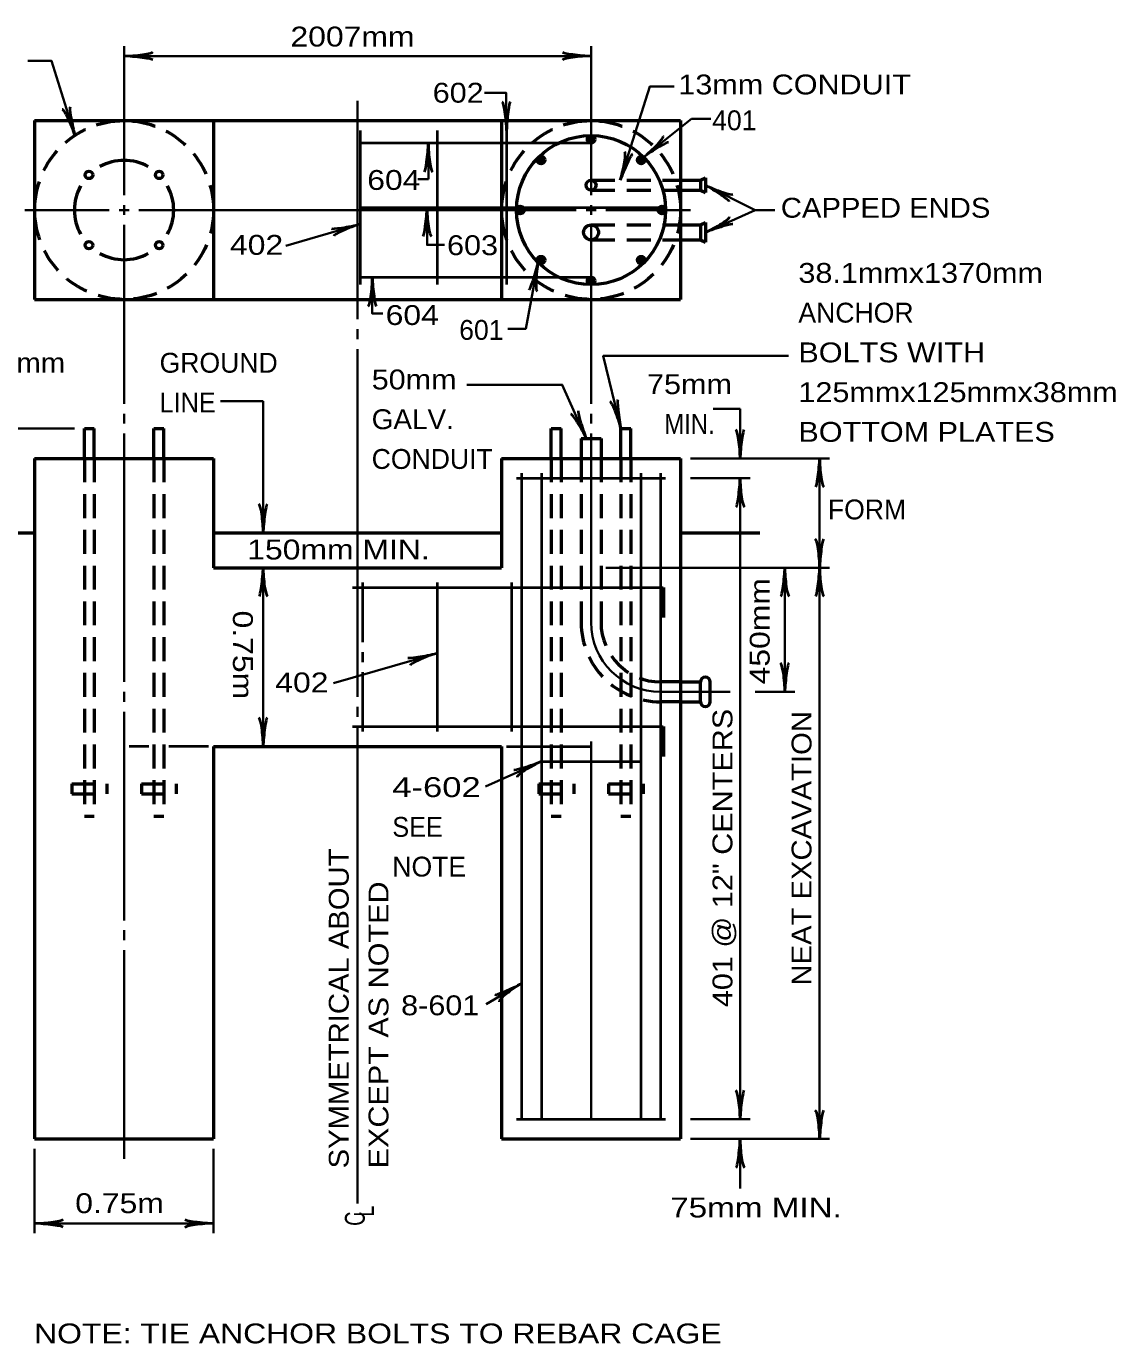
# Model space of a CAD drawing. Extents: x -35 to 821, y -13 to 531.
# Drawn here: x 522.5 to 654.1, y 256.5 to 415.6 of the extents above; entities that cross this region are included whole.
import ezdxf
from ezdxf.enums import TextEntityAlignment as Align

# ---------------------------------------------------------------- set-up
doc = ezdxf.new("R2010")
doc.units = 0
doc.header["$LTSCALE"] = 0.96
doc.linetypes.add('MEDIUM_DASHED', pattern=[4.5, 3, -1.5])
doc.layers.add('1', color=7, linetype='Continuous', lineweight=53)

msp = doc.modelspace()

# ---------------------------------------------------------------- hatches: boundary and pattern name
at = {"layer": '1'}
for points in [[(591.1548, 402.0095, 1), (590.2548, 402.0095, 1)], [(585.109, 399.5052, 1), (584.209, 399.5052, 1)], [(597.2006, 399.5053, 1), (596.3006, 399.5053, 1)], [(582.6048, 393.4595, 1), (581.7048, 393.4595, 1)], [(599.7048, 393.4595, 1), (598.8048, 393.4595, 1)], [(585.1089, 387.4136, 1), (584.2089, 387.4136, 1)], [(597.2007, 387.4138, 1), (596.3007, 387.4138, 1)], [(591.1548, 384.9095, 1), (590.2548, 384.9095, 1)]]:
    msp.add_hatch(color=256, dxfattribs=at).paths.add_polyline_path(points)

# ---------------------------------------------------------------- linework, layer by layer
at = {"layer": '1', "lineweight": 35}
for p, q in [((534.3048, 412.0595), (590.7048, 412.0595)), ((562.5048, 406.6595), (562.5048, 380.2595)), ((571.0542, 401.5321), (571.0542, 397.2018)), ((571.0542, 397.2018), (569.7716, 397.2018)), ((533.7048, 393.4595), (534.9048, 393.4595)), ((534.3048, 394.0595), (534.3048, 392.8595)), ((536.1048, 393.4595), (540.3048, 393.4595)), ((590.1048, 393.4595), (591.3048, 393.4595)), ((590.7048, 394.0595), (590.7048, 392.8595)), ((610.5048, 393.4595), (612.9048, 393.4595)), ((553.8453, 389.1457), (562.8048, 391.7477)), ((562.5048, 379.0595), (562.5048, 377.8595)), ((562.5048, 376.6595), (562.5048, 334.6595)), ((545.9299, 370.3554), (551.1048, 370.3554)), ((551.1048, 354.4595), (551.1048, 370.3554)), ((608.7048, 369.4595), (605.4636, 369.4595)), ((608.7048, 363.4595), (608.7048, 369.4595)), ((534.3048, 368.8595), (534.3048, 367.6595)), ((590.7048, 368.8595), (590.7048, 367.6595)), ((528.3048, 367.0595), (518.7048, 367.0595)), ((534.3048, 366.4595), (534.3048, 336.4595)), ((590.7048, 366.4595), (590.7048, 343.6595)), ((602.7048, 363.4595), (619.5048, 363.4595)), ((602.7048, 361.0595), (609.9048, 361.0595)), ((608.7048, 361.0595), (608.7048, 283.6595)), ((551.1048, 350.2595), (551.1048, 328.6595)), ((592.5048, 350.2595), (619.5048, 350.2595)), ((614.1048, 335.2595), (614.1048, 350.2595)), ((559.5972, 336.2975), (572.0184, 339.9048)), ((534.3048, 335.2595), (534.3048, 334.0595)), ((599.1048, 335.2595), (601.5048, 335.2595)), ((601.5048, 335.2595), (607.5048, 335.2595)), ((610.5048, 335.2595), (615.3048, 335.2595)), ((534.3048, 332.8595), (534.3048, 307.6595)), ((562.5048, 333.4595), (562.5048, 332.2595)), ((562.5048, 331.0595), (562.5048, 273.4595)), ((590.7048, 329.2595), (590.7048, 283.6595)), ((584.7048, 326.8595), (577.9613, 323.811)), ((534.3048, 306.4595), (534.3048, 305.2595)), ((534.3048, 304.0595), (534.3048, 278.8595)), ((582.3048, 300.045), (578.0516, 297.5282)), ((602.7048, 283.6595), (609.9048, 283.6595)), ((523.5048, 280.0595), (523.5048, 269.8595)), ((545.1048, 280.0595), (545.1048, 269.8595)), ((602.7048, 281.2595), (619.5048, 281.2595)), ((608.7048, 281.2595), (608.7048, 275.2595)), ((523.5048, 271.0595), (545.1048, 271.0595))]:
    msp.add_line(p, q, dxfattribs=at)
at = {"layer": '1'}
for p, q in [((523.5048, 404.2595), (601.5048, 404.2595)), ((523.5048, 404.2595), (523.5048, 382.6595)), ((545.1048, 404.2595), (545.1048, 382.6595)), ((579.9048, 404.2595), (579.9048, 382.6595)), ((601.5048, 404.2595), (601.5048, 382.6595)), ((601.5048, 397.0595), (603.9048, 397.0595)), ((603.9048, 397.0595), (604.5048, 397.3595)), ((603.9048, 397.0595), (603.9048, 395.8595)), ((604.5048, 397.3595), (604.5048, 395.5595)), ((601.5048, 395.8595), (603.9048, 395.8595)), ((603.9048, 395.8595), (604.5048, 395.5595)), ((601.5048, 391.6595), (603.9048, 391.6595)), ((603.9048, 391.6595), (604.5048, 391.9595)), ((603.9048, 391.6595), (603.9048, 389.8595)), ((604.5048, 391.9595), (604.5048, 389.5595)), ((601.5048, 389.8595), (603.9048, 389.8595)), ((603.9048, 389.8595), (604.5048, 389.5595)), ((523.5048, 382.6595), (601.5048, 382.6595)), ((529.5048, 363.4595), (529.5048, 367.0595)), ((529.5048, 367.0595), (530.7048, 367.0595)), ((530.7048, 363.4595), (530.7048, 367.0595)), ((537.9048, 363.4595), (537.9048, 367.0595)), ((537.9048, 367.0595), (539.1048, 367.0595)), ((539.1048, 363.4595), (539.1048, 367.0595)), ((585.9048, 363.4595), (585.9048, 367.0595)), ((585.9048, 367.0595), (587.1048, 367.0595)), ((587.1048, 363.4595), (587.1048, 367.0595)), ((594.3048, 363.4595), (594.3048, 367.0595)), ((594.3048, 367.0595), (595.5048, 367.0595)), ((595.5048, 363.4595), (595.5048, 367.0595)), ((589.5048, 365.8595), (591.9048, 365.8595)), ((589.5048, 365.8595), (589.5048, 363.4595)), ((591.9048, 365.8595), (591.9048, 363.4595)), ((523.5048, 363.4595), (523.5048, 281.2595)), ((523.5048, 363.4595), (545.1048, 363.4595)), ((545.1048, 363.4595), (545.1048, 350.2595)), ((579.9048, 363.4595), (601.5048, 363.4595)), ((579.9048, 363.4595), (579.9048, 350.2595)), ((601.5048, 363.4595), (601.5048, 281.2595)), ((504.9048, 354.4595), (523.5048, 354.4595)), ((545.1048, 354.4595), (579.9048, 354.4595)), ((601.5048, 354.4595), (611.1048, 354.4595)), ((545.1048, 350.2595), (579.9048, 350.2595)), ((601.5048, 336.4595), (603.9048, 336.4595)), ((603.9048, 334.0595), (603.9048, 336.4595)), ((605.1048, 334.0595), (605.1048, 336.4595)), ((601.5048, 334.0595), (603.9048, 334.0595)), ((545.1048, 328.6595), (579.9048, 328.6595)), ((545.1048, 328.6595), (545.1048, 281.2595)), ((579.9048, 328.6595), (579.9048, 281.2595)), ((523.5048, 281.2595), (545.1048, 281.2595)), ((579.9048, 281.2595), (601.5048, 281.2595))]:
    msp.add_line(p, q, dxfattribs=at)
at = {"layer": '1', "lineweight": 40}
for p, q in [((562.8048, 403.0595), (562.8048, 384.4595)), ((572.1048, 403.0595), (572.1048, 384.4595)), ((580.5048, 403.0595), (580.5048, 384.4595)), ((562.8048, 401.5595), (590.7048, 401.5595)), ((562.8048, 393.7595), (599.6998, 393.7595)), ((562.8048, 385.3595), (590.7048, 385.3595)), ((582.3048, 361.6595), (582.3048, 283.6595)), ((584.7048, 361.6595), (584.7048, 283.6595)), ((596.7048, 361.6595), (596.7048, 283.6595)), ((599.1048, 361.6595), (599.1048, 283.6595)), ((581.7048, 361.0595), (599.7048, 361.0595)), ((563.1048, 348.4595), (563.1048, 341.2595)), ((572.1048, 348.4595), (572.1048, 330.4595)), ((581.1048, 348.4595), (581.1048, 330.4595)), ((561.9048, 347.8595), (599.4048, 347.8595)), ((563.1048, 340.0595), (563.1048, 338.8595)), ((563.1048, 337.6595), (563.1048, 330.4595)), ((561.9048, 331.0595), (599.4048, 331.0595)), ((537.3048, 328.6595), (534.9048, 328.6595)), ((544.5048, 328.6595), (539.7048, 328.6595)), ((580.5048, 328.6595), (590.7048, 328.6595)), ((584.7048, 326.8595), (596.7048, 326.8595)), ((581.7048, 283.6595), (599.7048, 283.6595))]:
    msp.add_line(p, q, dxfattribs=at)
at = {"layer": '1', "linetype": 'MEDIUM_DASHED'}
for p, q in [((590.7048, 397.0595), (601.5048, 397.0595)), ((590.7048, 395.8595), (601.5048, 395.8595)), ((590.7048, 391.6595), (601.5048, 391.6595)), ((590.7048, 389.8595), (601.5048, 389.8595)), ((529.5048, 363.4595), (529.5048, 320.2595)), ((530.7048, 363.4595), (530.7048, 320.2595)), ((537.9048, 363.4595), (537.9048, 320.2595)), ((539.1048, 363.4595), (539.1048, 320.2595)), ((585.9048, 363.4595), (585.9048, 320.2595)), ((587.1048, 363.4595), (587.1048, 320.2595)), ((589.5048, 363.4595), (589.5048, 343.6595)), ((591.9048, 363.4595), (591.9048, 343.6595)), ((594.3048, 363.4595), (594.3048, 320.2595)), ((595.5048, 363.4595), (595.5048, 320.2595)), ((601.5048, 336.4595), (599.1048, 336.4595)), ((601.5048, 334.0595), (599.1048, 334.0595)), ((528.0048, 324.1595), (532.2048, 324.1595)), ((528.0048, 324.1595), (528.0048, 322.9595)), ((532.2048, 324.1595), (532.2048, 322.9595)), ((536.4048, 324.1595), (540.6048, 324.1595)), ((536.4048, 324.1595), (536.4048, 322.9595)), ((540.6048, 324.1595), (540.6048, 322.9595)), ((584.4048, 324.1595), (588.6048, 324.1595)), ((584.4048, 324.1595), (584.4048, 322.9595)), ((588.6048, 324.1595), (588.6048, 322.9595)), ((592.8048, 324.1595), (597.0048, 324.1595)), ((592.8048, 324.1595), (592.8048, 322.9595)), ((597.0048, 324.1595), (597.0048, 322.9595)), ((528.0048, 322.9595), (532.2048, 322.9595)), ((536.4048, 322.9595), (540.6048, 322.9595)), ((584.4048, 322.9595), (588.6048, 322.9595)), ((592.8048, 322.9595), (597.0048, 322.9595)), ((529.5048, 320.2595), (530.7048, 320.2595)), ((537.9048, 320.2595), (539.1048, 320.2595)), ((585.9048, 320.2595), (587.1048, 320.2595)), ((594.3048, 320.2595), (595.5048, 320.2595))]:
    msp.add_line(p, q, dxfattribs=at)
at = {"layer": '1', "lineweight": 60}
for p, q in [((599.4048, 347.8595), (599.4048, 344.2595)), ((599.4048, 331.0595), (599.4048, 327.4595))]:
    msp.add_line(p, q, dxfattribs=at)
at = {"layer": '1', "lineweight": 35}
for points in [[(534.3048, 395.2595), (534.3048, 399.4595), (534.3048, 413.2595)], [(590.7048, 395.2595), (590.7048, 402.4595), (590.7048, 413.2595)], [(528.3644, 402.479), (525.5393, 411.4708), (522.6973, 411.4708)], [(580.5048, 403.0595), (580.4546, 407.6008), (577.8259, 407.6008)], [(594.2289, 397.0595), (597.7948, 408.3695), (600.7229, 408.3695)], [(597.0539, 399.8383), (602.8488, 404.4656), (605.1742, 404.4656)], [(604.5048, 396.4595), (610.5048, 393.4595), (604.5048, 390.7595)], [(532.5048, 393.4595), (528.3048, 393.4595), (522.3048, 393.4595)], [(540.3048, 393.4595), (581.7048, 393.4595), (588.9048, 393.4595)], [(570.8939, 393.7595), (570.8939, 389.247), (573.0102, 389.247)], [(592.5048, 393.4595), (599.7048, 393.4595), (602.7048, 393.4595)], [(534.3048, 391.6595), (534.3048, 387.4595), (534.3048, 370.0595)], [(590.7048, 391.6595), (590.7048, 384.4595), (590.7048, 370.0595)], [(584.3069, 387.1297), (582.8194, 379.1177), (580.6439, 379.1177)], [(564.2863, 385.2834), (564.2863, 380.9531), (565.5689, 380.9531)], [(594.3048, 367.0595), (592.1755, 375.8564), (614.5294, 375.8564)], [(590.1236, 365.8595), (587.2269, 372.3571), (575.7136, 372.3571)], [(618.3048, 363.4595), (618.3048, 350.2595), (618.3048, 281.2595)]]:
    msp.add_lwpolyline(points, dxfattribs=at)
at = {"layer": '1', "linetype": 'MEDIUM_DASHED'}
for centre in [(534.3048, 393.4595), (590.7048, 393.4595)]:
    msp.add_circle(centre, 10.8, dxfattribs=at)
at = {"layer": '1'}
for centre, radius in [((590.7048, 393.4595), 9), ((590.7048, 402.0095), 0.45), ((584.659, 399.5052), 0.45), ((596.7506, 399.5053), 0.45), ((530.0622, 397.7021), 0.45), ((538.5474, 397.7021), 0.45), ((590.7048, 396.4595), 0.6), ((582.1548, 393.4595), 0.45), ((599.2548, 393.4595), 0.45), ((590.7048, 390.7595), 0.9), ((530.0622, 389.2169), 0.45), ((538.5474, 389.2169), 0.45), ((584.6589, 387.4136), 0.45), ((596.7507, 387.4138), 0.45), ((590.7048, 384.9095), 0.45)]:
    msp.add_circle(centre, radius, dxfattribs=at)
for centre, radius, start, end in [((534.3048, 393.4595), 6, 60.95954, 119.04116), ((534.3048, 393.4595), 6, 150.96024, 209.04046), ((534.3048, 393.4595), 6, 330.95884, 29.04046), ((534.3048, 393.4595), 6, 240.95954, 299.03976), ((604.5048, 336.4235), 0.6011, 3.43671, 176.56329), ((604.5048, 334.0955), 0.6011, 183.43671, 356.56329)]:
    msp.add_arc(centre, radius, start, end, dxfattribs=at)
at = {"layer": '1', "linetype": 'MEDIUM_DASHED'}
for radius in [9.6, 7.2]:
    msp.add_arc((599.1048, 343.6595), radius, 180, 270, dxfattribs=at)
at = {"layer": '1', "lineweight": 35}
msp.add_arc((599.1048, 343.6595), 8.4, 180, 270, dxfattribs=at)
at = {"layer": '1', "lineweight": 40}
for centre, major_axis, ratio, start_param, end_param in [((535.6142, 412.3911), (-2.1428, -0.1874), 0.122415, 0.89635335, 3.14159265), ((535.6142, 412.3911), (-2.1428, -0.1874), 0.122415, 0.89635335, 3.14159265), ((589.3602, 412.3134), (2.1077, -0.2108), 0.07063, 3.14071475, 5.41810995), ((535.6494, 411.8056), (-2.1077, 0.2108), 0.07063, 3.14071475, 5.41810995), ((535.6494, 411.8056), (-2.1077, 0.2108), 0.07063, 3.14071475, 5.41810995), ((589.3954, 411.7279), (2.1428, 0.1874), 0.122415, 0.89635335, 3.14159265), ((528.2036, 403.8379), (0.4307, -2.074), 0.07063, 3.14071475, 5.41810995), ((580.1588, 404.3652), (0.2111, -2.1406), 0.122415, 0.89635335, 3.14159265), ((580.7438, 404.4068), (-0.1875, -2.1099), 0.07063, 3.14071475, 5.41810995), ((527.6556, 403.6289), (0.8211, -1.9881), 0.122415, 0.89635335, 3.14159265), ((570.8003, 400.1875), (0.2108, 2.1077), 0.07063, 3.14071475, 5.41810995), ((571.3858, 400.2227), (-0.1874, 2.1428), 0.122415, 0.89635335, 3.14159265), ((597.8703, 400.9145), (-1.5576, -1.4835), 0.122415, 0.89635335, 3.14159265), ((598.2631, 400.4789), (1.7786, 1.1505), 0.07063, 6.28230741, 8.55970261), ((594.3064, 398.408), (-0.4656, -2.1), 0.122415, 0.89635335, 3.14159265), ((594.8754, 398.2655), (0.8348, 1.9468), 0.07063, 6.28230741, 8.55970261), ((605.5939, 395.6311), (-1.791, 1.1311), 0.07063, 3.14071475, 5.41810995), ((605.5939, 395.6311), (-1.791, 1.1311), 0.07063, 3.14071475, 5.41810995), ((605.8243, 396.1705), (-2.0004, 0.7907), 0.122415, 0.89635335, 3.14159265), ((605.8243, 396.1705), (-2.0004, 0.7907), 0.122415, 0.89635335, 3.14159265), ((570.64, 392.4149), (0.2108, 2.1077), 0.07063, 3.14071475, 5.41810995), ((571.2255, 392.4501), (-0.1874, 2.1428), 0.122415, 0.89635335, 3.14159265), ((561.4427, 391.6165), (-2.0829, -0.3854), 0.07063, 6.28230741, 8.55970261), ((561.6398, 391.0641), (2.0056, 0.7776), 0.122415, 0.89635335, 3.14159265), ((605.5628, 391.5992), (-1.8772, -1.0502), 0.122415, 0.89635335, 3.14159265), ((605.8352, 391.0797), (-2.0086, -0.6727), 0.07063, 3.14071475, 5.41810995), ((583.8118, 385.854), (-0.592, -2.0339), 0.07063, 6.28230741, 8.55970261), ((584.3939, 385.7817), (0.2069, 2.141), 0.122415, 0.89635335, 3.14159265), ((563.9547, 383.974), (0.1874, 2.1428), 0.122415, 3.14159265, 5.38683196), ((564.5402, 383.9388), (-0.2108, 2.1077), 0.07063, 0.86507535, 3.14247055), ((589.808, 367.191), (0.6657, -2.0109), 0.07063, 3.14071475, 5.41810995), ((593.6745, 368.2542), (0.6862, -2.0386), 0.122415, 0.89635335, 3.14159265), ((594.2353, 368.4261), (0.291, -2.0982), 0.07063, 3.14071475, 5.41810995), ((589.2876, 366.9205), (1.0437, -1.8809), 0.122415, 0.89635335, 3.14159265), ((608.3732, 364.7689), (0.1874, -2.1428), 0.122415, 0.89635335, 3.14159265), ((608.9587, 364.8041), (-0.2108, -2.1077), 0.07063, 3.14071475, 5.41810995), ((618.0509, 362.1149), (0.2108, 2.1077), 0.07063, 3.14071475, 5.41810995), ((618.0509, 362.1149), (0.2108, 2.1077), 0.07063, 3.14071475, 5.41810995), ((618.6364, 362.1501), (-0.1874, 2.1428), 0.122415, 0.89635335, 3.14159265), ((618.6364, 362.1501), (-0.1874, 2.1428), 0.122415, 0.89635335, 3.14159265), ((608.4509, 359.7149), (0.2108, 2.1077), 0.07063, 3.14071475, 5.41810995), ((609.0364, 359.7501), (-0.1874, 2.1428), 0.122415, 0.89635335, 3.14159265), ((550.7732, 355.7689), (0.1874, -2.1428), 0.122415, 0.89635335, 3.14159265), ((551.3587, 355.8041), (-0.2108, -2.1077), 0.07063, 3.14071475, 5.41810995), ((617.9732, 351.5689), (0.1874, -2.1428), 0.122415, 0.89635335, 3.14159265), ((617.9732, 351.5689), (0.1874, -2.1428), 0.122415, 0.89635335, 3.14159265), ((618.5587, 351.6041), (-0.2108, -2.1077), 0.07063, 3.14071475, 5.41810995), ((618.5587, 351.6041), (-0.2108, -2.1077), 0.07063, 3.14071475, 5.41810995), ((550.8509, 348.9149), (0.2108, 2.1077), 0.07063, 3.14071475, 5.41810995), ((550.8509, 348.9149), (0.2108, 2.1077), 0.07063, 3.14071475, 5.41810995), ((551.4364, 348.9501), (-0.1874, 2.1428), 0.122415, 0.89635335, 3.14159265), ((551.4364, 348.9501), (-0.1874, 2.1428), 0.122415, 0.89635335, 3.14159265), ((613.8509, 348.9149), (0.2108, 2.1077), 0.07063, 3.14071475, 5.41810995), ((613.8509, 348.9149), (0.2108, 2.1077), 0.07063, 3.14071475, 5.41810995), ((614.4364, 348.9501), (-0.1874, 2.1428), 0.122415, 0.89635335, 3.14159265), ((614.4364, 348.9501), (-0.1874, 2.1428), 0.122415, 0.89635335, 3.14159265), ((618.0509, 348.9149), (0.2108, 2.1077), 0.07063, 3.14071475, 5.41810995), ((618.0509, 348.9149), (0.2108, 2.1077), 0.07063, 3.14071475, 5.41810995), ((618.6364, 348.9501), (-0.1874, 2.1428), 0.122415, 0.89635335, 3.14159265), ((618.6364, 348.9501), (-0.1874, 2.1428), 0.122415, 0.89635335, 3.14159265), ((570.6563, 339.7736), (-2.0829, -0.3854), 0.07063, 6.28230741, 8.55970261), ((570.8534, 339.2212), (2.0056, 0.7776), 0.122415, 0.89635335, 3.14159265), ((613.7732, 336.5689), (0.1874, -2.1428), 0.122415, 0.89635335, 3.14159265), ((613.7732, 336.5689), (0.1874, -2.1428), 0.122415, 0.89635335, 3.14159265), ((614.3587, 336.6041), (-0.2108, -2.1077), 0.07063, 3.14071475, 5.41810995), ((614.3587, 336.6041), (-0.2108, -2.1077), 0.07063, 3.14071475, 5.41810995), ((550.7732, 329.9689), (0.1874, -2.1428), 0.122415, 0.89635335, 3.14159265), ((551.3587, 330.0041), (-0.2108, -2.1077), 0.07063, 3.14071475, 5.41810995), ((583.375, 326.537), (-2.0074, -0.6762), 0.07063, 6.28230741, 8.55970261), ((583.6482, 326.018), (1.8754, 1.0534), 0.122415, 0.89635335, 3.14159265), ((581.0183, 299.5788), (1.9213, 0.892), 0.07063, 3.14071475, 5.41810995), ((581.3467, 299.0928), (1.7487, 1.2525), 0.122415, 0.89635335, 3.14159265), ((608.3732, 284.9689), (0.1874, -2.1428), 0.122415, 0.89635335, 3.14159265), ((608.3732, 284.9689), (0.1874, -2.1428), 0.122415, 0.89635335, 3.14159265), ((608.9587, 285.0041), (-0.2108, -2.1077), 0.07063, 3.14071475, 5.41810995), ((608.9587, 285.0041), (-0.2108, -2.1077), 0.07063, 3.14071475, 5.41810995), ((617.9732, 282.5689), (0.1874, -2.1428), 0.122415, 0.89635335, 3.14159265), ((617.9732, 282.5689), (0.1874, -2.1428), 0.122415, 0.89635335, 3.14159265), ((618.5587, 282.6041), (-0.2108, -2.1077), 0.07063, 3.14071475, 5.41810995), ((618.5587, 282.6041), (-0.2108, -2.1077), 0.07063, 3.14071475, 5.41810995), ((608.4509, 279.9149), (0.2108, 2.1077), 0.07063, 3.14071475, 5.41810995), ((609.0364, 279.9501), (-0.1874, 2.1428), 0.122415, 0.89635335, 3.14159265), ((524.8494, 270.8056), (-2.1077, 0.2108), 0.07063, 3.14071475, 5.41810995), ((524.8494, 270.8056), (-2.1077, 0.2108), 0.07063, 3.14071475, 5.41810995), ((524.8142, 271.3911), (-2.1428, -0.1874), 0.122415, 0.89635335, 3.14159265), ((524.8142, 271.3911), (-2.1428, -0.1874), 0.122415, 0.89635335, 3.14159265), ((543.7954, 270.7279), (2.1428, 0.1874), 0.122415, 0.89635335, 3.14159265), ((543.7602, 271.3134), (2.1077, -0.2108), 0.07063, 3.14071475, 5.41810995)]:
    msp.add_ellipse(centre, major_axis=major_axis, ratio=ratio, start_param=start_param, end_param=end_param, dxfattribs=at)

# ---------------------------------------------------------------- texts
at = {"layer": '1'}
for s, width, p in [('2007mm', 1.2, (554.3963, 413.2097)), ('13mm CONDUIT', 1.15, (601.2396, 407.4218)), ('602', 1.15, (571.5768, 406.4279)), ('604', 1.2, (563.6689, 395.8906)), ('CAPPED ENDS', 1.1, (613.6226, 392.5314)), ('402', 1.2, (547.0946, 388.0499)), ('603', 1.15, (573.3087, 388.009)), ('38.1mmx1370mm', 1.15, (615.7446, 384.6621)), ('604', 1.2, (565.8928, 379.5724)), ('BOLTS WITH', 1.15, (615.7446, 375.0621)), ('125mm', 1.1, (515.4131, 373.808)), ('50mm', 1.15, (564.2092, 371.7909)), ('125mmx125mmx38mm', 1.15, (615.7446, 370.2621)), ('LINE', 0.95, (538.5955, 369.0101)), ('GALV.', 1.05, (564.2092, 366.9909)), ('BOTTOM PLATES', 1.15, (615.7446, 365.4621)), ('150mm MIN.', 1.2, (549.1796, 351.2499)), ('402', 1.2, (552.5653, 335.199)), ('4-602', 1.3, (566.6996, 322.553)), ('SEE', 0.95, (566.6996, 317.753)), ('8-601', 1.15, (567.765, 296.1997)), ('0.75m', 1.2, (528.4055, 272.2967)), ('75mm MIN.', 1.25, (600.2622, 271.7738)), ('NOTE: TIE ANCHOR BOLTS TO REBAR CAGE', 1.2, (523.4368, 256.5679))]:
    msp.add_text(s, height=2.4, dxfattribs=dict(at, width=width)).set_placement(p)
for s, p in [('401', (605.3267, 403.0957)), ('ANCHOR', (615.7446, 379.8621)), ('601', (574.778, 377.7794)), ('GROUND', (538.5955, 373.8101)), ('CONDUIT', (564.2092, 362.1909)), ('FORM', (619.308, 356.0927)), ('NOTE', (566.6996, 312.953))]:
    msp.add_text(s, height=2.4, dxfattribs=at).set_placement(p)
for s, width, p in [('75mm', 1.15, (602.5887, 371.2263)), ('MIN.', 0.9, (602.5887, 366.4263))]:
    msp.add_text(s, height=2.4, dxfattribs=dict(at, width=width)).set_placement(p, align=Align.CENTER)
for s, rotation, width, p in [('450mm', 90, 1.2, (612.2722, 336.1615)), ('0.75m', 270, 1.2, (547.455, 345.0801)), ('401 @ 12" CENTERS', 90, 1.15, (607.7757, 297.181)), ('NEAT EXCAVATION', 90, 1.1, (617.326, 299.7865)), ('SYMMETRICAL ABOUT', 90, 1.1, (561.4326, 277.7023)), ('EXCEPT AS NOTED', 90, 1.15, (566.2326, 277.7023)), ('C', 90, 0.75, (563.3737, 270.7545)), ('L', 90, 0.75, (564.49, 271.8711))]:
    msp.add_text(s, height=2.4, rotation=rotation, dxfattribs=dict(at, width=width)).set_placement(p)

doc.saveas('drawing.dxf')
